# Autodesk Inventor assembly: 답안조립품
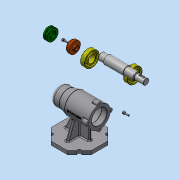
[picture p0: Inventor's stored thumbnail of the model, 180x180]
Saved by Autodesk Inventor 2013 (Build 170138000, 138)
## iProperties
Created: 2019-12
Part Number: 답안조립품
Document SubType Name: Assembly
Designer: Administrator
Author: Administrator
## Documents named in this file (7)
- C:\Users\Administrator\Desktop\491204V1033\답안조립품.iam
- C:\Users\Administrator\Desktop\491204V1033\본체.ipt
- C:\Users\Administrator\Desktop\491204V1033\베어링 6004.ipt
- C:\Users\Administrator\Desktop\491204V1033\축.ipt
- C:\Users\Administrator\Desktop\491204V1033\어댑터슬리브.ipt
- C:\Users\Administrator\Desktop\491204V1033\볼트 M4.ipt
- C:\Users\Administrator\Desktop\491204V1033\베어링 51202.ipt
